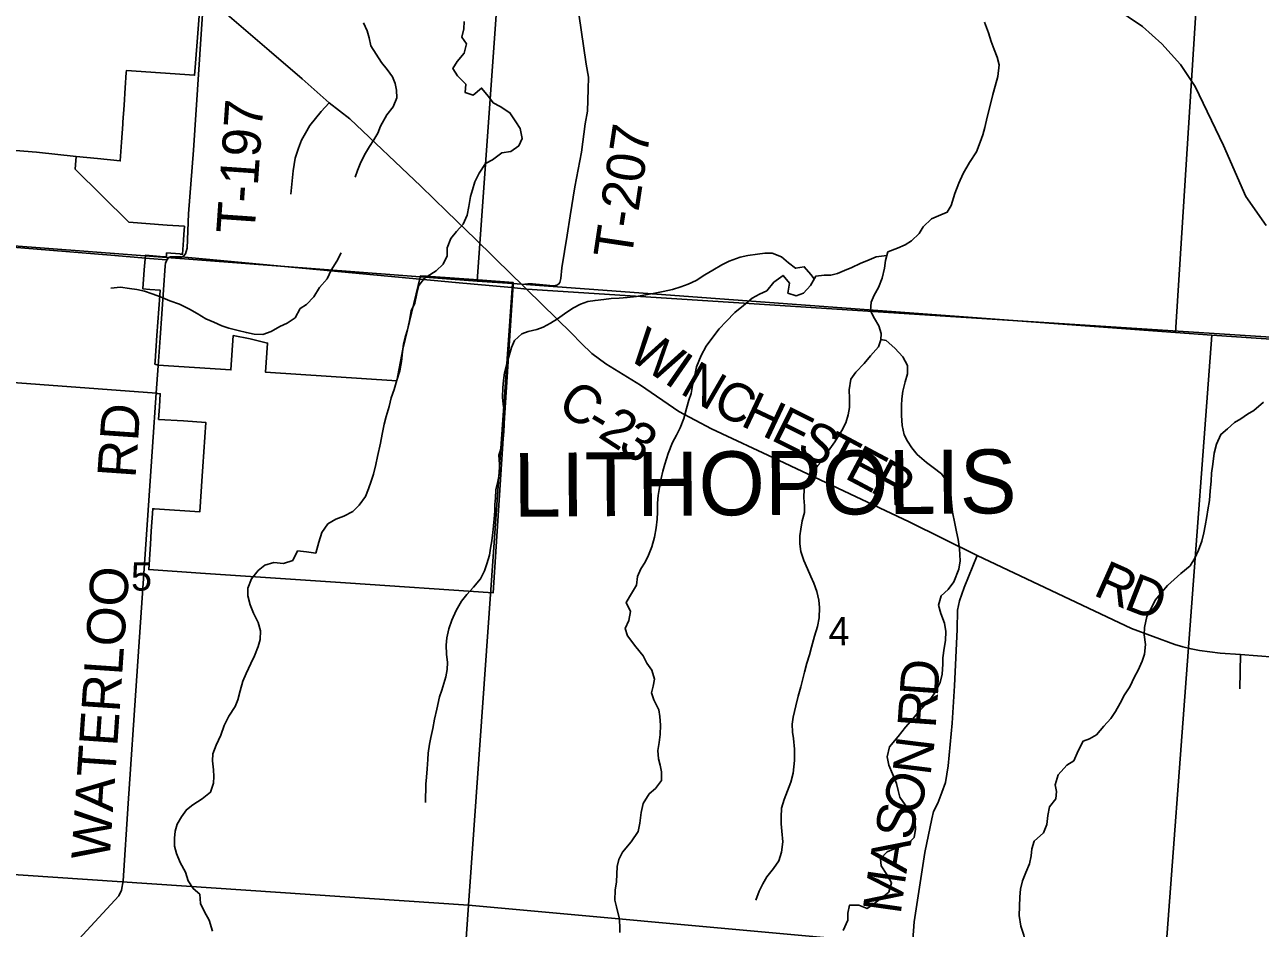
# Model space of a CAD drawing. Extents: x 114843 to 284848, y 317643 to 566895.
# Drawn here: x 263305 to 272976, y 330933 to 338001 of the extents above; entities that cross this region are included whole.
import ezdxf

# ---------------------------------------------------------------- set-up
doc = ezdxf.new("R2010")
doc.units = 0
for name, color, linetype in [('GM_X_Corporation', 7, 'Continuous'), ('GM_X_Corporation_Text', 7, 'Continuous'), ('GM_X_County_Road', 7, 'Continuous'), ('GM_X_County_Road_Text', 7, 'Continuous'), ('GM_X_Minor_River', 7, 'Continuous'), ('GM_X_Rail_Line', 7, 'Continuous'), ('GM_X_Section', 7, 'Continuous'), ('GM_X_Section_Text', 7, 'Continuous'), ('GM_X_Township', 7, 'Continuous'), ('GM_X_Township_Road', 7, 'Continuous'), ('GM_X_Township_Road_Text', 7, 'Continuous')]:
    doc.layers.add(name, color=color, linetype=linetype)

msp = doc.modelspace()

# ---------------------------------------------------------------- linework, layer by layer
at = {"layer": 'GM_X_Corporation'}
for points in [[(263291.6, 339602.1), (263880.9, 339027.1), (263827.7, 338311.4), (264169.7, 338291.8), (264179.9, 338445.1), (264198, 338716.8), (264439.5, 338480.4), (264684.7, 338240.5), (264639.6, 337665.6), (264634.9, 337605.7), (264101.1, 337641.8), (264100, 337626.4), (264092, 337507.1), (264082.9, 337372.4), (264073.8, 337237.7), (264072.8, 337223.3), (264063.3, 337083.1), (264053.3, 336935.7), (263874.7, 336953.9), (263707.5, 336971), (263707.4, 336971), (263397.7, 337005.1), (263065.7, 337029.8)], [(263065.7, 337029.8), (263397.7, 337005.1), (263707.5, 336971), (263702.1, 336903.9), (263699.5, 336871.4), (264118.7, 336456.5), (264420.2, 336434), (264555, 336423.9), (264550.7, 336359.3), (264547.7, 336315.4), (264540.4, 336205.8), (264522.3, 336207.2), (264519.9, 336207.3), (264415.8, 336215.1), (264415.5, 336210.1), (264413.8, 336185.2), (264365.8, 336188.8), (264249.2, 336197.4), (264241, 336082.1), (264230.4, 335934.6), (264283.8, 335930.6), (264365, 335924.5), (264362.1, 335883.1), (264339.6, 335569.6), (264325.2, 335368.7), (264323.5, 335345.6), (264350.6, 335337.8), (264919.4, 335299.9), (264937.3, 335569.2), (265069.6, 335544.5), (265195.5, 335513.1), (265205.8, 335510.6), (265190.6, 335282.2), (266216.4, 335214), (266263.5, 335463.6), (266402.5, 336036.3), (266450.9, 336032.8), (266484.2, 336030.4), (266854.9, 336004.2), (267128.8, 335984.2), (267127.6, 335966.3), (267104.7, 335607.9), (266972.5, 333556.8), (265815.1, 333635), (264679.6, 333711.8), (264275.2, 333739.1), (264288.4, 333938.7), (264294.9, 334038.5), (264306.5, 334214.9), (264320.5, 334214), (264675.8, 334190.6), (264693.8, 334469.3), (264698.8, 334544.7), (264721.7, 334890), (264549, 334901), (264352.5, 334913.5), (264359.1, 335015), (264365.6, 335114.6), (264347.1, 335115.8), (264335.9, 335116.5), (264336, 335118.3), (262963, 335221.1)]]:
    msp.add_lwpolyline(points, dxfattribs=at)
at = {"layer": 'GM_X_County_Road'}
msp.add_line((267118.5, 336045), (267196.3, 335969), dxfattribs=at)
for points in [[(264706.5, 338244.9), (264742.8, 338210.7), (264853.2, 338112.6), (265219.5, 337797.9), (265475.7, 337576.6), (265687.4, 337390), (265850.4, 337263.5), (266405.8, 336738.1), (266609.5, 336540.3), (266834.5, 336322.1), (267118.5, 336045)], [(267196.3, 335969), (267235.9, 335930.4), (267585.5, 335589.2), (267659.3, 335509), (267743.9, 335428.7), (267853.4, 335348.5), (268125.3, 335182.4), (268425.5, 334974.4), (268681.6, 334839.3), (269206.1, 334594.1), (270228.6, 334111.3), (270760.8, 333850)], [(270760.8, 333850), (271968.6, 333276.5), (272307.5, 333152.8), (272370.5, 333134), (272434.5, 333118.4), (272499.2, 333106.3), (272580.5, 333095), (272662.2, 333086), (272821.4, 333074.2), (273087.8, 333054.6), (273227.9, 333045.6), (273442.7, 333029.2), (273898.1, 332996), (274109, 332952.8), (274350.6, 332764.1), (276438.6, 330746.9)]]:
    msp.add_lwpolyline(points, dxfattribs=at)
at = {"layer": 'GM_X_Minor_River'}
for points in [[(266743.7, 338025.5), (266741.5, 337969.5), (266727.3, 337903.5), (266763, 337851.3), (266744.8, 337777.3), (266688.7, 337713.5), (266656.5, 337659.5), (266692.2, 337601.4), (266757.8, 337535.1), (266751.6, 337471.1), (266815.4, 337448.9), (266881.4, 337504.7), (266935.1, 337440.5), (266970.8, 337390.3), (267026.6, 337360.1), (267102.2, 337311.8), (267149.8, 337241.7), (267183.6, 337189.5), (267199.2, 337111.4), (267173.1, 337053.4), (267109, 337009.6), (267039.2, 336997.8), (266965.1, 336944), (266911.1, 336914.2), (266860.9, 336840.3), (266828.8, 336772.3), (266808.6, 336710.3), (266794.4, 336656.3), (266782.1, 336578.3), (266767.9, 336512.3), (266735.7, 336440.4), (266685.6, 336384.5), (266639.5, 336328.6), (266611.3, 336256.6), (266611, 336192.6), (266578.9, 336128.6), (266524.8, 336076.7), (266434.8, 336017), (266388.7, 335961.1), (266374.5, 335899.1), (266358.2, 335823.1), (266330, 335763.1), (266315.8, 335687.1), (266301.5, 335613.1), (266283.4, 335557.1), (266269.2, 335501.1), (266261, 335443.1), (266254.7, 335367), (266240.4, 335293), (266218.2, 335221), (266196, 335147.1), (266173.8, 335081.1), (266157.6, 335015.1), (266133.3, 334937.1), (266119.1, 334875.1), (266102.8, 334797.1), (266090.6, 334727), (266066.3, 334623), (266052.1, 334561), (266033.8, 334485), (266017.6, 334431), (265995.4, 334369), (265973.3, 334309.1), (265923.1, 334241.2), (265873.1, 334193.3), (265803.1, 334157.5), (265741.1, 334133.7), (265677.1, 334095.8), (265631, 334027.9), (265606.7, 333951.9), (265582.5, 333867.9), (265510.7, 333878.2), (265440.8, 333884.4), (265402.6, 333810.5), (265330.7, 333786.7)], [(265955.5, 338016), (265985.2, 337953.9), (266000.9, 337897.8), (266014.7, 337835.7), (266056.3, 337771.5), (266098, 337705.3), (266141.7, 337651.2), (266183.4, 337593), (266205.1, 337540.9), (266214.9, 337488.8), (266216.6, 337428.8), (266188.4, 337358.8), (266140.3, 337294.9), (266090.1, 337207), (266069.9, 337153), (266037.8, 337099.1), (266003.7, 337047.1), (265965.5, 336983.2), (265929.3, 336913.3), (265909.2, 336859.3), (265891, 336807.3)], [(270816.5, 338020.5), (270848.2, 337938.4), (270869.9, 337870.3), (270893.6, 337806.1), (270917.3, 337746), (270931, 337685.9), (270920.7, 337595.9), (270900.4, 337519.9), (270882.2, 337455.9), (270857.9, 337357.9), (270837.7, 337277.9), (270819.4, 337195.9), (270803.2, 337139.9), (270783, 337082), (270754.8, 337006), (270700.6, 336924.1), (270650.4, 336838.2), (270616.2, 336760.3), (270586, 336680.3), (270555.7, 336586.3), (270525.5, 336534.4), (270457.6, 336504.6), (270401.6, 336482.7), (270337.5, 336418.9), (270305.4, 336366.9), (270245.3, 336311.1), (270195.3, 336279.2), (270137.3, 336253.4), (270061.4, 336223.6), (270041.2, 336157.6), (270035, 336097.6), (270016.7, 336017.6), (269986.5, 335945.6), (269954.3, 335885.7), (269930.2, 335829.7), (269925.9, 335763.7), (269955.6, 335701.5), (269991.3, 335645.4), (270009.1, 335585.3), (270006.9, 335535.2), (269986.7, 335481.2), (269924.6, 335409.4), (269874.5, 335349.5), (269810.4, 335281.6), (269770.2, 335227.7), (269758, 335145.7), (269761.7, 335075.6), (269759.4, 335005.6), (269749.2, 334949.6), (269731, 334887.6), (269700.9, 334825.6), (269644.6, 334737.7), (269594.5, 334665.8), (269562.3, 334607.9), (269512.2, 334552), (269468.1, 334496.1), (269434, 334440.1), (269405.8, 334370.2), (269403.5, 334300.1), (269409.3, 334236), (269407.1, 334186), (269390.9, 334120), (269378.6, 334054), (269372.5, 334001.9), (269372.2, 333939.9), (269380, 333879.8), (269403.7, 333809.7), (269431.3, 333745.5), (269459, 333685.4), (269480.8, 333633.3), (269504.5, 333567.1), (269520.2, 333499), (269526, 333441), (269523.7, 333360.9)], [(263980, 335938.8), (264053.8, 335946.5), (264125.7, 335938.3), (264181.5, 335930.1), (264243.3, 335915.9), (264303.1, 335895.7), (264366.9, 335871.5), (264440.6, 335841.2), (264516.3, 335814.9), (264594, 335774.7), (264655.7, 335742.4), (264723.4, 335700.2), (264785.2, 335674), (264848.9, 335645.8), (264902.7, 335627.6), (264974.5, 335609.3), (265040.3, 335593.1), (265100.1, 335580.9), (265169.9, 335576.7), (265233.9, 335600.5), (265301.9, 335640.3), (265359.8, 335666.1), (265421.9, 335708), (265460, 335779.9), (265510.1, 335811.8), (265568.2, 335871.6), (265612.3, 335945.6), (265672.5, 336013.4), (265702.7, 336081.4), (265746.8, 336151.3), (265783, 336215.2)], [(269484.6, 336012.9), (269458.1, 336047.4), (269406.4, 336107.6), (269338.5, 336095.8), (269282.8, 336138), (269229.1, 336186.2), (269155.4, 336212.5), (269097.5, 336212.7), (269039.6, 336206.8), (268965.7, 336195.1), (268905.8, 336183.2), (268819.9, 336151.5), (268761.9, 336121.7), (268691.9, 336079.8), (268627.9, 336044), (268559.9, 336000.2), (268497.9, 335970.4), (268440, 335950.6), (268374.1, 335930.7), (268302.2, 335915), (268224.3, 335899.2), (268164.4, 335887.4), (268092.5, 335875.6), (268020.6, 335867.8), (267956.7, 335862), (267894.9, 335860.2), (267839, 335852.4), (267769.1, 335844.6), (267713.2, 335834.8), (267655.2, 335814.9), (267599.3, 335785.1), (267547.2, 335753.2), (267475.2, 335699.4), (267421.2, 335665.6), (267363.2, 335633.7), (267313.3, 335617.9), (267245.4, 335602.1), (267195.4, 335582.2), (267139.3, 335530.4), (267115.2, 335476.4), (267092.9, 335402.4), (267078.8, 335350.4), (267060.5, 335278.4), (267052.3, 335216.4), (267046.1, 335160.3), (267045.8, 335088.3), (267049.6, 335032.2), (267057.4, 334980.2), (267057, 334870.1), (267054.8, 334818), (267048.6, 334762), (267038.4, 334706), (267016.2, 334634), (267019.9, 334563.9), (267021.6, 334491.9), (267007.4, 334427.9), (266991.2, 334361.9), (266989, 334299.8), (266984.8, 334247.8), (266984.6, 334197.7), (266978.3, 334135.7), (266974.1, 334081.7), (266968, 334027.6), (266961.7, 333963.6), (266951.5, 333905.6), (266943.3, 333851.6), (266921.1, 333783.6), (266903, 333729.6), (266872.8, 333665.6), (266816.7, 333599.8), (266764.6, 333543.9), (266722.5, 333492), (266682.3, 333418), (266648.1, 333344.1), (266623.9, 333276.1), (266607.6, 333204.1), (266603.4, 333148.1), (266607.1, 333076), (266612.9, 333011.9), (266610.7, 332957.9), (266600.5, 332899.9), (266586.3, 332847.8), (266570.1, 332795.9), (266552, 332741.9), (266531.7, 332645.9), (266513.4, 332567.8), (266499.2, 332495.8), (266484.9, 332425.8), (266472.8, 332371.8), (266462.5, 332303.8), (266460.3, 332251.7), (266456, 332179.7), (266449.8, 332113.6), (266443.6, 332059.6), (266443.1, 331915.5)], [(270052.5, 336194.6), (269969.4, 336183.9), (269915.5, 336162), (269843.5, 336132.2), (269779.6, 336102.4), (269721.6, 336078.6), (269665.6, 336054.7), (269613.7, 336040.9), (269561.8, 336041), (269495.9, 336033.3), (269455.7, 335961.3), (269401.6, 335901.5), (269343.7, 335879.6), (269277.9, 335901.8), (269292.2, 335977.9), (269240.5, 336040.1), (269168.5, 335986.3), (269112.4, 335918.4), (269056.4, 335892.5), (268998.4, 335862.7), (268930.3, 335804.9), (268864.3, 335749), (268794.2, 335679.2), (268740.1, 335621.3), (268691.9, 335555.4), (268639.8, 335487.5), (268599.6, 335413.6), (268563.3, 335325.6), (268547.1, 335245.6), (268532.8, 335177.6), (268520.6, 335115.6), (268502.5, 335063.6), (268484.3, 334997.6), (268464, 334921.6), (268435.8, 334847.7), (268405.6, 334789.7), (268375.5, 334733.8), (268341.2, 334647.8), (268315, 334563.8), (268300.8, 334507.8), (268286.6, 334449.8), (268274.4, 334381.8), (268264.2, 334317.8), (268257.9, 334257.7), (268257.7, 334187.7), (268255.5, 334133.6), (268247.2, 334065.6), (268235, 333991.6), (268212.7, 333915.6), (268186.6, 333851.6), (268162.4, 333795.6), (268128.3, 333743.7), (268102.1, 333685.7), (268093.9, 333615.7), (268053.7, 333551.8), (268011.5, 333479.8), (268045.2, 333411.7), (268032.9, 333339.6), (268004.8, 333277.7), (268022.5, 333221.6), (268088, 333135.3), (268145.6, 333065), (268173.4, 333006.9), (268213.1, 332950.7), (268234.7, 332880.6), (268222.6, 332826.6), (268210.4, 332774.6), (268230.1, 332718.5), (268267.7, 332640.3), (268275.5, 332590.2), (268281.3, 332522.1), (268279, 332448.1), (268270.8, 332386), (268260.5, 332324), (268264.3, 332257.9), (268278.1, 332207.9), (268289.8, 332155.8), (268289.6, 332089.7), (268241.5, 332025.8), (268191.4, 331983.9), (268145.2, 331910), (268131, 331838), (268120.7, 331756), (268106.5, 331689.9), (268052.3, 331608.1), (267984.1, 331528.2), (267954, 331470.2), (267941.8, 331416.2), (267937.4, 331296.1), (267927.1, 331230.1), (267922.8, 331152.1), (267936.6, 331100), (267958.2, 331013.8), (267962, 330951.8), (267963.8, 330899.7)], [(270007, 335538.7), (270046.8, 335531.1), (270116.4, 335470.8), (270178, 335402.6), (270213.6, 335334.4), (270213.4, 335270.3), (270195.2, 335208.4), (270179, 335134.4), (270170.7, 335074.3), (270168.6, 335022.3), (270166.3, 334944.2), (270172, 334866.1), (270187.6, 334792), (270213.4, 334741.9), (270249.1, 334689.7), (270290.8, 334639.6), (270362.4, 334577.3), (270414.1, 334537.1), (270479.8, 334488.8), (270531.4, 334420.6), (270553, 334328.5), (270558.8, 334260.4), (270566.5, 334188.3), (270584.1, 334100.2), (270597.8, 334034.1), (270611.6, 333974), (270621.3, 333899.9), (270626.9, 333807.8), (270616.7, 333741.7), (270578.4, 333643.8), (270532.3, 333583.9), (270478.2, 333534), (270457.9, 333460), (270475.7, 333395.9), (270505.3, 333319.7), (270515, 333253.6), (270510.8, 333183.6), (270502.6, 333123.6), (270492.3, 333049.5), (270492.1, 332999.5), (270485.8, 332919.4), (270469.6, 332855.4), (270437.4, 332787.4), (270387.3, 332713.6), (270305.1, 332631.7), (270255, 332571.8), (270198.9, 332506), (270142.7, 332432.1), (270074.6, 332352.2), (270056.3, 332274.2), (270068, 332208.1), (270097.7, 332140), (270129.4, 332065.8), (270141.1, 332011.7), (270154.9, 331959.6), (270196.6, 331897.4), (270254.1, 331819.2), (270275.8, 331757), (270277.7, 331707), (270267.4, 331643), (270209.4, 331589.1), (270157.4, 331569.3), (270105.4, 331551.4), (270055.5, 331529.5), (270003.4, 331475.7), (270007.2, 331421.6), (270052.8, 331353.4), (270090.5, 331289.2), (270068.3, 331215.2), (270016.2, 331173.4), (269952.2, 331123.5), (269898.1, 331087.7), (269832.4, 331113.9), (269760.6, 331114.1), (269746.3, 331052.1), (269748.1, 330996.1), (269709.9, 330916.1)], [(273000.3, 335047.3), (272926.2, 334983.5), (272876.2, 334953.6), (272824.2, 334917.7), (272774.2, 334887.9), (272718.1, 334840), (272666.1, 334796.1), (272633.9, 334720.2), (272615.6, 334648.2), (272605.3, 334564.1), (272595.1, 334494.1), (272590.8, 334430.1), (272584.6, 334354), (272578.3, 334280), (272566, 334205.9), (272557.9, 334153.9), (272543.6, 334079.9), (272533.4, 334025.9), (272517.2, 333961.9), (272493, 333889.9), (272462.8, 333827.9), (272426.7, 333768), (272354.6, 333708.2), (272302.6, 333660.3), (272250.5, 333614.4), (272204.4, 333562.5), (272152.3, 333498.6), (272116.1, 333424.7), (272087.9, 333370.7), (272069.6, 333286.7), (272067.4, 333228.6), (272077.1, 333152.5), (272068.8, 333076.5), (272050.7, 333022.5), (272020.5, 332952.5), (271992.3, 332900.6), (271954.1, 332820.6), (271912, 332758.7), (271879.8, 332692.8), (271841.7, 332628.8), (271805.5, 332574.9), (271751.4, 332513), (271693.3, 332447.1), (271639.3, 332415.3), (271589.3, 332395.4), (271551.1, 332321.5), (271516.9, 332243.5), (271460.9, 332209.7), (271392.8, 332133.8), (271370.5, 332053.8), (271380.3, 332003.7), (271376.1, 331945.7), (271326, 331881.8), (271313.7, 331813.8), (271305.5, 331745.7), (271279.3, 331679.8), (271205.2, 331613.9), (271187, 331553.9), (271182.8, 331499.9)], [(265330.7, 333786.7), (265254.9, 333794.9), (265185, 333773.1), (265131, 333731.3), (265080.8, 333667.4), (265050.6, 333593.4), (265052.4, 333533.4), (265070.1, 333463.2), (265095.8, 333397.1), (265131.4, 333324.9), (265151.1, 333258.8), (265146.9, 333190.8), (265132.7, 333136.8), (265102.5, 333062.8), (265074.3, 333002.8), (265038.1, 332926.9), (265011.9, 332866.9), (264991.7, 332790.9), (264973.4, 332720.9), (264953.3, 332666.9), (264903.1, 332591), (264864.9, 332519.1), (264840.7, 332443.1), (264802.5, 332365.2), (264778.3, 332297.2), (264774.1, 332243.1), (264781.8, 332171.1), (264785.6, 332119), (264783.4, 332067), (264759.2, 331997), (264693.1, 331945.2), (264621.1, 331897.3), (264571.1, 331859.5), (264531, 331805.5), (264498.8, 331747.6), (264482.6, 331693.6), (264476.4, 331637.6), (264478.2, 331575.5), (264493.9, 331517.4), (264521.6, 331447.3), (264563.2, 331371.1), (264584.9, 331305), (264624.6, 331244.8), (264676.3, 331198.6), (264680, 331126.5), (264711.7, 331060.3), (264749.4, 330996.2), (264775, 330910)], [(269523.7, 333360.9), (269509.4, 333292.9), (269487.2, 333218.9), (269462.9, 333132.9), (269446.7, 333072.9), (269426.5, 333006.9), (269408.3, 332936.9), (269396.1, 332882.9), (269379.9, 332820.9), (269359.7, 332748.9), (269339.5, 332672.9), (269319.2, 332582.9), (269313, 332528.8), (269314.7, 332466.8), (269322.5, 332416.7), (269330.2, 332332.6), (269329.8, 332244.5), (269319.5, 332146.5), (269301.3, 332076.5), (269275.1, 332008.5), (269248.9, 331940.5), (269228.7, 331872.5), (269224.4, 331802.5), (269226.2, 331750.4), (269232, 331692.3), (269237.6, 331608.2), (269229.3, 331528.2), (269207.1, 331460.2), (269165, 331400.3), (269112.9, 331334.4), (269082.7, 331280.5), (269052.6, 331222.5), (269026.4, 331152.5)], [(271182.8, 331499.9), (271170.6, 331437.9), (271140.4, 331367.9), (271114.2, 331304), (271100, 331239.9), (271093.8, 331177.9), (271091.5, 331101.8), (271087.3, 331031.8), (271100.9, 330949.7), (271124.6, 330879.5), (271140.3, 330807.4), (271116, 330713.4), (271065.9, 330659.5), (270993.9, 330625.7), (270939.8, 330563.9), (270887.7, 330500), (270807.7, 330456.2), (270725.7, 330412.4), (270667.7, 330378.6), (270619.5, 330306.7), (270623.3, 330240.6), (270623, 330172.5), (270600.8, 330114.5), (270566.7, 330050.6)]]:
    msp.add_lwpolyline(points, dxfattribs=at)
at = {"layer": 'GM_X_Rail_Line'}
msp.add_lwpolyline([(271829, 338137.4), (272052.6, 337987.3), (272204, 337851), (272350.7, 337690.6), (272466, 337516.2), (272688.1, 337056.6), (272862.9, 336657.3), (273020.5, 336429.8)], dxfattribs=at)
at = {"layer": 'GM_X_Section'}
for points in [[(267232.2, 341404.2), (272656.8, 341014.8), (272313.4, 335594.4), (267122.9, 335976.7), (266846.8, 335995.7)], [(272656.8, 341014.8), (277988.7, 340646.3), (277608.8, 335233.2), (272595.5, 335573.5), (272313.4, 335594.4)], [(261644.3, 336390), (266846.8, 335995.7), (267122.9, 335976.7), (266777.3, 331114.5), (261314.9, 331481.8)], [(267122.9, 335976.7), (272313.4, 335594.4), (272595.5, 335573.5), (272226.3, 330617.1), (266777.3, 331114.5)], [(272595.5, 335573.5), (277608.8, 335233.2), (277905, 335210.8), (277566.7, 330233.9), (272226.3, 330617.1)], [(261314.9, 331481.8), (266777.3, 331114.5), (266403.7, 325730.1), (260975.3, 326089.6)], [(266777.3, 331114.5), (272226.3, 330617.1), (271824.5, 325260.5), (266403.7, 325730.1)]]:
    msp.add_lwpolyline(points, close=True, dxfattribs=at)
at = {"layer": 'GM_X_Township'}
for points in [[(284847.9, 334827.1), (284589.8, 334841.1), (282084.6, 334989.6), (280932.5, 335069.7), (280906.1, 335067.3), (279738.3, 335118.8), (274192.7, 335483.3), (267234.7, 335933.2), (267114.6, 335944.4), (266677.9, 335985), (264530.1, 336184.9), (264473.3, 336185.9), (264446.8, 336185), (264429.2, 336179), (264415.2, 336161.7), (264282.1, 336172.6), (263978.7, 336197.5), (262021.1, 336357.8)], [(262021.1, 336357.8), (263978.7, 336197.5), (264282.1, 336172.6), (264415.2, 336161.7), (264429.2, 336179), (264446.8, 336185), (264473.3, 336185.9), (264530.1, 336184.9), (266677.9, 335985), (267114.6, 335944.4), (267234.7, 335933.2), (274192.7, 335483.3), (279738.3, 335118.8), (280906.1, 335067.3), (280932.5, 335069.7), (282084.6, 334989.6), (284589.8, 334841.1), (284847.9, 334827.1)]]:
    msp.add_lwpolyline(points, dxfattribs=at)
at = {"layer": 'GM_X_Township_Road'}
for p, q in [((264334.9, 335122.1), (264349.2, 335331.5)), ((272814.4, 332805.6), (272821.4, 333074.2))]:
    msp.add_line(p, q, dxfattribs=at)
for points in [[(267714.4, 337495.6), (267717.1, 337589.4), (267699.2, 337691.8), (267642.9, 338086.7), (267621, 338242), (267610.3, 338304.1), (267578.6, 338378.1), (267535.6, 338431.9), (267490.3, 338470.8), (267445.1, 338507.6), (267428.7, 338585.1), (267426.5, 338594.8)], [(264515.8, 336182.4), (264531.2, 336182.1), (264551, 336193.3), (264563.4, 336208.1), (264569.2, 336226.5), (264575.6, 336253.8), (264585.9, 336521.1), (264625.3, 337018.6), (264706.5, 338244.9)], [(267549.7, 336353.5), (267573.1, 336504.8), (267611.3, 336732.2), (267662.5, 337002.7), (267691.3, 337224.9), (267709.5, 337323.7), (267714.4, 337495.6)], [(265388.8, 336675.8), (265405.4, 336857), (265420.9, 336955.7), (265447.2, 337034.7), (265471.8, 337097.6), (265501.9, 337151.6), (265535.4, 337212.8), (265624.3, 337321), (265687.4, 337390)], [(267196.3, 335969), (267243.5, 335974.6), (267259.2, 335974.7), (267279, 335974.3), (267444.2, 335958.3), (267470.2, 335962.2), (267485.8, 335972.7), (267492.5, 335983.2), (267501.3, 336015.9), (267510, 336097.8), (267549.7, 336353.5)], [(264349.2, 335331.5), (264364.3, 335551.4), (264403.8, 336114.3), (264407.1, 336136.2), (264416.4, 336158.9), (264419.9, 336163.2)], [(264419.9, 336163.2), (264430.4, 336176.2), (264448, 336182.2), (264474.5, 336183.1), (264515.8, 336182.4)], [(264180.7, 332868.5), (264305.9, 334698.1), (264334.9, 335122.1)], [(269950.2, 329045.9), (270151, 329763), (270176.7, 329919.2), (270217.9, 330311.9), (270266.6, 330982.9), (270349.5, 331525.9), (270405, 331788.3), (270418.9, 331846.4), (270452.8, 331910.6), (270482.6, 331994.8), (270512.5, 332073), (270532.2, 332203.2), (270563.5, 332537.8), (270582.9, 332830.2), (270604.1, 333268.9), (270605.8, 333421.1), (270621.6, 333495.2), (270657.4, 333597.5), (270760.8, 333850)], [(263481.2, 330580.2), (264041.6, 331186.4), (264062.9, 331231.8), (264076.2, 331302.8), (264115.1, 331909.2), (264180.7, 332868.5)]]:
    msp.add_lwpolyline(points, dxfattribs=at)

# ---------------------------------------------------------------- texts
at = {"layer": 'GM_X_Corporation_Text'}
msp.add_text('LITHOPOLIS', height=500.04, rotation=0.41458, dxfattribs=at).set_placement((267131.4, 334151))
at = {"layer": 'GM_X_County_Road_Text'}
for s, rotation, p in [('W', 326.54345, (268011.6, 335396.7)), ('I', 325.26529, (268300.1, 335206)), ('N', 329.92728, (268423.9, 335121.5)), ('C', 325.21857, (267459.4, 334995.2)), ('C', 334.11917, (268673.6, 334978)), ('H', 334.75768, (268898.5, 334868.8)), ('2', 326.9699, (267783, 334781)), ('E', 333.52758, (269135.8, 334757)), ('-', 328.95909, (267679.8, 334843)), ('3', 325.89455, (267936.7, 334681)), ('S', 332.2854, (269335.2, 334657.7)), ('T', 331.98065, (269514, 334563.8)), ('E', 331.97996, (269712.1, 334458.4)), ('R', 331.98107, (269910.3, 334352.9)), ('R', 335.99526, (271658.8, 333542.9)), ('D', 338.65535, (271897.7, 333436.8))]:
    msp.add_text(s, height=300, rotation=rotation, dxfattribs=at).set_placement(p)
at = {"layer": 'GM_X_Section_Text'}
for s, rotation, p in [('5', 0.41451, (264137.4, 333573.5)), ('4', 0.41462, (269597.1, 333145.4))]:
    msp.add_text(s, height=221, rotation=rotation, dxfattribs=at).set_placement(p)
at = {"layer": 'GM_X_Township_Road_Text'}
for s, height, rotation, p in [('T-197', 300.03, 86.01561, (265102.9, 336357.9)), ('T-207', 300.03, 81.4571, (268052.3, 336158.4)), ('RD', 300.03, 86.01573, (264171.7, 334449.4)), ('WATERLOO', 300.03, 86.11001, (263968.9, 331461.4)), ('D', 300, 86.00613, (270451.6, 332738.7)), ('R', 300, 86.00782, (270434.4, 332492.9)), ('N', 300, 82.93913, (270394, 332120.6)), ('O', 300, 69.73278, (270284.8, 331799.7)), ('S', 300, 78.06564, (270246.1, 331612.7)), ('A', 300, 80.93311, (270205.2, 331355.9)), ('M', 300, 81.98123, (270160, 331034.9))]:
    msp.add_text(s, height=height, rotation=rotation, dxfattribs=at).set_placement(p)

doc.saveas('drawing.dxf')
